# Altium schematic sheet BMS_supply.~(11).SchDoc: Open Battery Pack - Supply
size A4; Date: 26/03/2019; Author: Morgane Vallée - Samuel Lesueur; Revision: 1.0; SheetNumber: 2; SheetTotal: 4
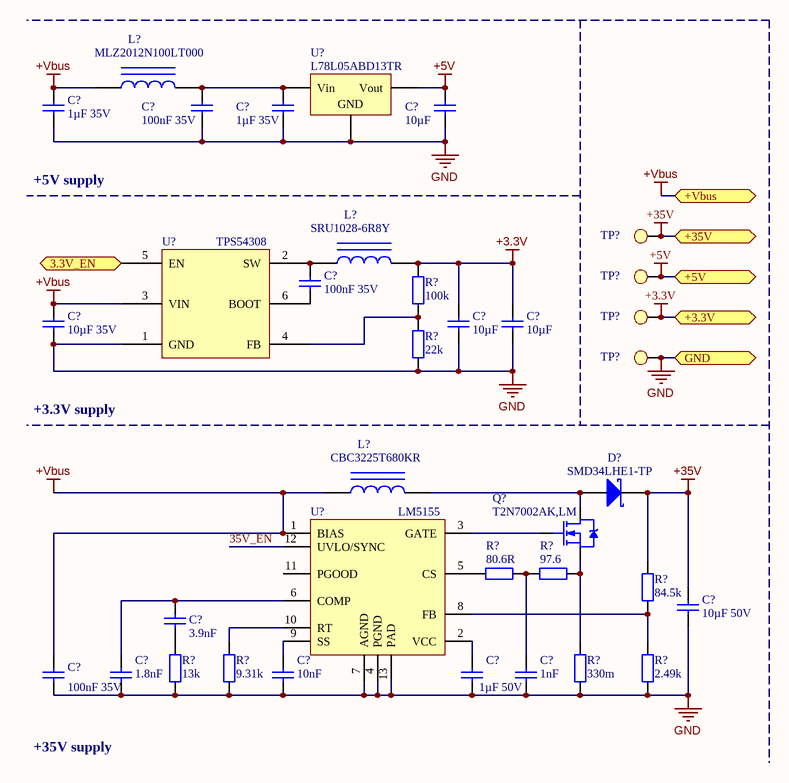
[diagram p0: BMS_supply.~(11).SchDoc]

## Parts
(Parts that share a designator on the sheet are numbered #1, #2 ... from top to bottom, then left to right.)
C?#1  1µF 35V  [C0805]
C?#2  100nF 35V  [C0603]
C?#3  1µF 35V  [C0805]
C?#4  10µF  [C0603]
C?#5  100nF 35V  [C0603]
C?#6  10µF 35V  [C0805]
C?#7  10µF  [C0603]
C?#8  10µF  [C0603]
C?#9  10µF 50V  [C0603]
C?#10  3.9nF  [C0603]
C?#11  100nF 35V  [C0603]
C?#12  1.8nF  [C0603]
C?#13  10nF  [C0603]
C?#14  1µF 50V  [C0805]
C?#15  1nF  [C0603]
D?  SMD34LHE1-TP  [SOD-123H]
L?#1  MLZ2012N100LT000  [FER 0805/2012]
L?#2  SRU1028-6R8Y  [FER 0805/2012]
L?#3  CBC3225T680KR  [SELF_SMD_8x8]
Q?  T2N7002AK,LM  [TI SOT-23-3 DBZ]
R?#1  100k  [R0603]
R?#2  22k  [R0603]
R?#3  80.6R  [R0603]
R?#4  97.6  [R0603]
R?#5  84.5k  [R0603]
R?#6  13k  [R0603]
R?#7  9.31k  [R0603]
R?#8  330m  [R1206]
R?#9  2.49k  [R0603]
TP?#1  Test Point  [Test Point]  (value not drawn)
TP?#2  Test Point  [Test Point]  (value not drawn)
TP?#3  Test Point  [Test Point]  (value not drawn)
TP?#4  Test Point  [Test Point]  (value not drawn)
U?#1  L78L05ABD13TR  [ST SOIC-8N]
U?#2  TPS54308  [TI SOT-23-6 DDC]
U?#3  LM5155  [TI WSON-12]

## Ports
3.3V_EN (in), +3.3V, +5V, +35V, +Vbus, GND

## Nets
+3.3V: C?#7.1 C?#8.1 L?#2.2 R?#1.2 TP?#3.1 ; port +3.3V
+5V: C?#4.1 TP?#2.1 U?#1.3(Vout) ; port +5V
+35V: C?#9.1 D?.3(K) R?#5.2 TP?#1.1 ; port +35V
+Vbus: C?#1.1 C?#6.1 C?#11.1 L?#1.1 L?#3.1 U?#2.3(VIN) U?#3.1(BIAS) ; port +Vbus
GND: C?#1.2 C?#2.2 C?#3.2 C?#4.2 C?#6.2 C?#7.2 C?#8.2 C?#9.2 C?#11.2 C?#12.2 C?#13.2 C?#14.2 C?#15.2 R?#2.1 R?#6.1 R?#7.1 R?#8.1 R?#9.1 TP?#4.1 U?#1.2(GND) U?#2.1(GND) U?#3.4(PGND) U?#3.7(AGND) U?#3.13(PAD) ; port GND
3.3V_EN: U?#2.5(EN) ; port 3.3V_EN
35V_EN: U?#3.12(UVLO/SYNC)
NetC?#2_1: C?#2.1 C?#3.1 L?#1.2 U?#1.1(Vin)
NetC?#5_1: C?#5.1 L?#2.1 U?#2.2(SW)
NetC?#5_2: C?#5.2 U?#2.6(BOOT)
NetC?#10_1: C?#10.1 C?#12.1 U?#3.6(COMP)
NetC?#10_2: C?#10.2 R?#6.2
NetC?#13_1: C?#13.1 U?#3.9(SS)
NetC?#14_1: C?#14.1 U?#3.2(VCC)
NetC?#15_1: C?#15.1 R?#3.1 R?#4.2
NetD?_1: D?.1(A) L?#3.2 Q?.3(D)
NetQ?_1: Q?.1(G) U?#3.3(GATE)
NetQ?_2: Q?.2(S) R?#4.1 R?#8.2
NetR?#1_1: R?#1.1 R?#2.2 U?#2.4(FB)
NetR?#3_2: R?#3.2 U?#3.5(CS)
NetR?#5_1: R?#5.1 R?#9.2 U?#3.8(FB)
NetR?#7_2: R?#7.2 U?#3.10(RT)

Not connected (* = marked no-connect by the designer): U?#3 11(PGOOD)

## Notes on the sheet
- +5V supply
- +3.3V supply
- +35V supply

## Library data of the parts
C?#1-C?#15 = Cap: Capacitor
D? = Diode BAT17
L?#1-L?#3 = Inductor Iron: Magnetic-Core Inductor
Q? = MOSFET_N
R?#1-R?#9 = Res2: Resistor
U?#1 = Volt Reg: Voltage Regulator; pin to pad: 1>8 2>2+3+6+7 3>1
U?#2 = TPS54308: 4.5-V to 28-V Input, 3-A Output,  Synchronous 350-kHz FCCM Step-Down Converter in SOT23 Package
U?#3 = LM5155: 2.2-MHz Wide Input Nonsynchronous Boost, SEPIC, Flyback Controller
